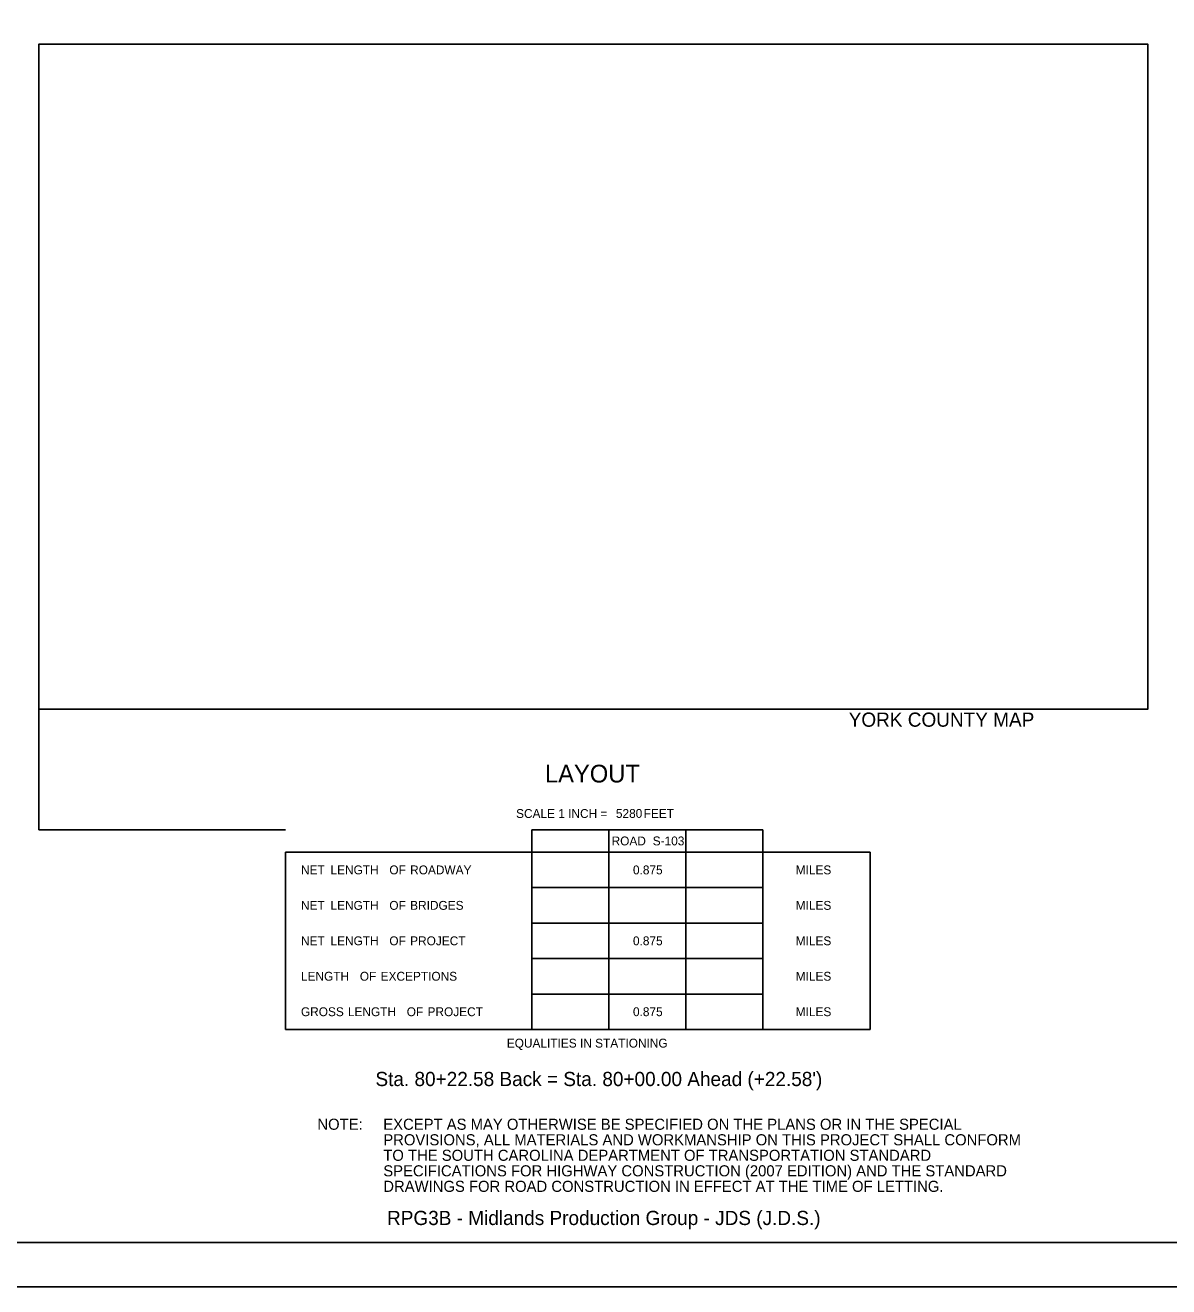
# Model space of a CAD drawing. Extents: x 8134 to 11793, y 3225 to 13425.
# Drawn here: x 10596 to 11241, y 10000 to 10711 of the extents above; entities that cross this region are included whole.
import ezdxf

# ---------------------------------------------------------------- set-up
doc = ezdxf.new("R2010")
doc.units = 0
for name, color, linetype in [('GN_TitleSheetMap', 7, 'Continuous'), ('RD_SHT_Bndy', 7, 'Continuous'), ('RD_SHT_IplotShp', 7, 'Continuous'), ('RD_SHT_TX', 7, 'Continuous'), ('RD_TX_StaOff', 7, 'Continuous'), ('RD_TX_TitleSht', 7, 'Continuous')]:
    doc.layers.add(name, color=color, linetype=linetype)

msp = doc.modelspace()

# ---------------------------------------------------------------- linework, layer by layer
at = {"layer": 'GN_TitleSheetMap'}
msp.add_lwpolyline([(10603.73, 10325.6), (11228.73, 10325.6), (11228.73, 10700.6), (10603.73, 10700.6)], close=True, dxfattribs=at)
at = {"layer": 'RD_SHT_Bndy'}
for p, q in [((10603.73, 10325.6), (10603.73, 10257.68)), ((10742.67, 10257.68), (10603.73, 10257.68)), ((10881.61, 10257.68), (11011.77, 10257.68)), ((10881.61, 10145.07), (10881.61, 10257.68)), ((10925, 10145.07), (10925, 10257.68)), ((10968.38, 10145.07), (10968.38, 10257.68)), ((11011.77, 10145.07), (11011.77, 10257.68)), ((10742.67, 10245), (11072.22, 10245)), ((10742.67, 10145.07), (10742.67, 10245)), ((11072.22, 10145.07), (11072.22, 10245)), ((10881.61, 10225.02), (11011.77, 10225.02)), ((10881.61, 10205.03), (11011.77, 10205.03)), ((10881.61, 10185.04), (11011.77, 10185.04)), ((10881.61, 10165.05), (11011.77, 10165.05)), ((10742.67, 10145.07), (11072.22, 10145.07)), ((10000, 10000), (11759.98, 10000)), ((11760, 10000), (10000, 10000))]:
    msp.add_line(p, q, dxfattribs=at)
msp.add_lwpolyline([(10079.63, 11075.05), (11755.13, 11075.05), (11755.13, 10025), (10079.63, 10025)], close=True, dxfattribs=at)
at = {"layer": 'RD_SHT_IplotShp'}
msp.add_lwpolyline([(9984.13, 11100), (11780.13, 11100), (11780.13, 10000), (9984.13, 10000)], close=True, dxfattribs=at)
at = {"layer": 'RD_TX_StaOff'}
msp.add_line((10742.67, 10257.68), (10742.67, 10257.68), dxfattribs=at)

# ---------------------------------------------------------------- texts
at = {"layer": 'RD_SHT_TX'}
for s, height, p in [('LAYOUT', 10, (10888.97, 10284.3)), ('SCALE 1 INCH =           FEET', 5, (10872.7, 10264.3)), ('ROAD', 5, (10926.54, 10248.84)), (' S-103', 5, (10947.86, 10248.84)), ('NET', 5, (10751.45, 10232.51)), (' LENGTH', 5, (10766.24, 10232.51)), (' OF', 5, (10799.41, 10232.51)), (' ROADWAY', 5, (10811.14, 10232.51)), ('0.875', 5, (10938.58, 10232.51)), ('MILES', 5, (11030.31, 10232.51)), ('NET', 5, (10751.45, 10212.52)), (' LENGTH', 5, (10766.24, 10212.52)), (' OF', 5, (10799.41, 10212.52)), (' BRIDGES', 5, (10811.14, 10212.52)), ('MILES', 5, (11030.31, 10212.52)), ('NET', 5, (10751.45, 10192.53)), (' LENGTH', 5, (10766.24, 10192.53)), (' OF', 5, (10799.41, 10192.53)), (' PROJECT', 5, (10811.14, 10192.53)), ('0.875', 5, (10938.58, 10192.53)), ('MILES', 5, (11030.31, 10192.53)), ('LENGTH', 5, (10751.45, 10172.55)), (' OF', 5, (10782.78, 10172.55)), (' EXCEPTIONS', 5, (10794.51, 10172.55)), ('MILES', 5, (11030.31, 10172.55)), ('GROSS', 5, (10751.45, 10152.56)), (' LENGTH', 5, (10776.04, 10152.56)), (' OF', 5, (10809.21, 10152.56)), (' PROJECT', 5, (10820.94, 10152.56)), ('0.875', 5, (10938.58, 10152.56)), ('MILES', 5, (11030.31, 10152.56)), ('EQUALITIES IN STATIONING', 5.0001, (10867.47, 10134.85)), ('NOTE:     EXCEPT AS MAY OTHERWISE BE SPECIFIED ON THE PLANS OR IN THE SPECIAL ', 6.2499, (10760.7, 10088.5)), ('                PROVISIONS, ALL MATERIALS AND WORKMANSHIP ON THIS PROJECT SHALL CONFORM ', 6.2499, (10760.7, 10079.75)), ('                TO THE SOUTH CAROLINA DEPARTMENT OF TRANSPORTATION STANDARD ', 6.2499, (10760.7, 10071)), ('                SPECIFICATIONS FOR HIGHWAY CONSTRUCTION (2007 EDITION) AND THE STANDARD', 6.2499, (10760.7, 10062.25)), ('                DRAWINGS FOR ROAD CONSTRUCTION IN EFFECT AT THE TIME OF LETTING.', 6.2499, (10760.7, 10053.5))]:
    msp.add_text(s, height=height, dxfattribs=at).set_placement(p)
at = {"layer": 'RD_TX_TitleSht'}
for s, height, p in [('YORK COUNTY MAP', 8, (11060.18, 10315.73)), ('5280', 5, (10928.96, 10264.34)), ("Sta. 80+22.58 Back = Sta. 80+00.00 Ahead (+22.58')", 8, (10793.44, 10113.14)), ('RPG3B - Midlands Production Group - JDS (J.D.S.)', 8, (10799.98, 10034.8))]:
    msp.add_text(s, height=height, dxfattribs=at).set_placement(p)

doc.saveas('drawing.dxf')
